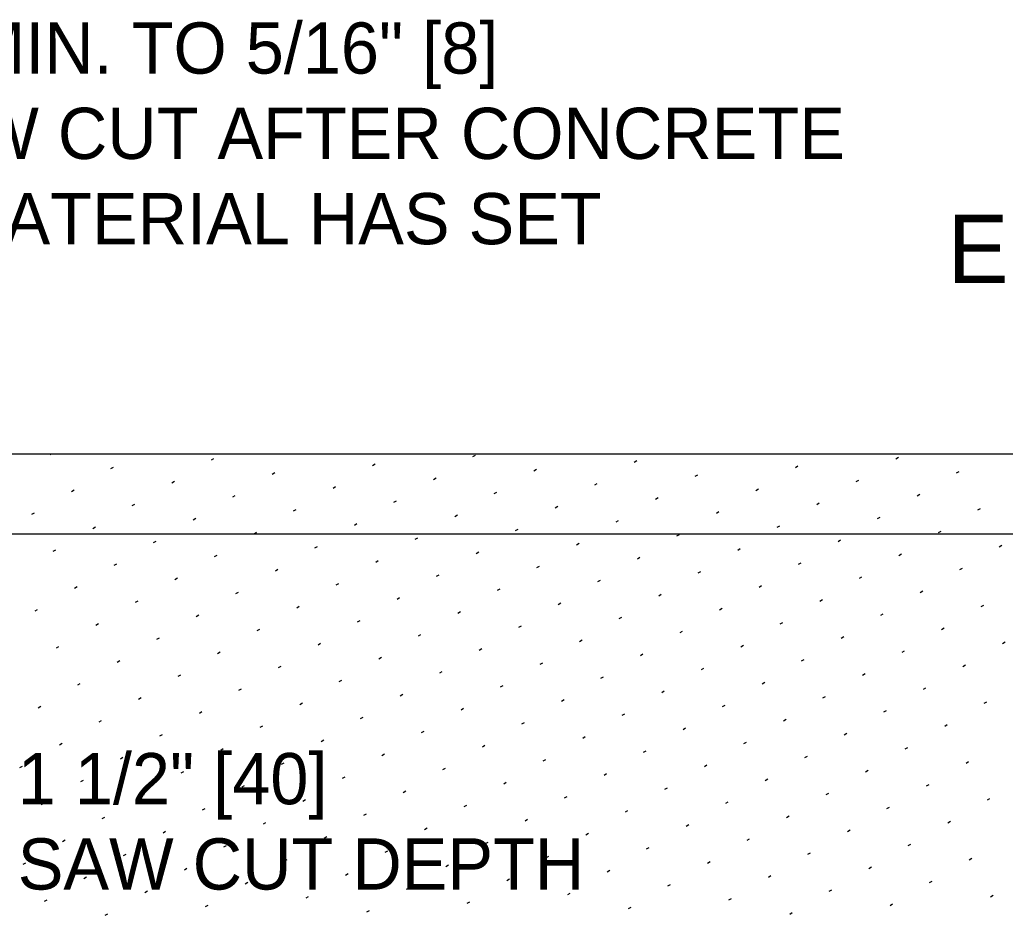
# Model space of a CAD drawing. Extents: x 49991.4 to 50021, y 49987.6 to 50011.4.
# Drawn here: x 50008.715 to 50009.87, y 49994.336 to 49995.386 of the extents above; entities that cross this region are included whole.
import ezdxf

# ---------------------------------------------------------------- set-up
doc = ezdxf.new("R2010")
doc.units = 0
for name, color, linetype in [('Level 1', 7, 'Continuous'), ('Level 2', 7, 'Continuous'), ('Level 3', 7, 'Continuous'), ('Level 6', 7, 'Continuous')]:
    doc.layers.add(name, color=color, linetype=linetype)

msp = doc.modelspace()

# ---------------------------------------------------------------- linework, layer by layer
at = {"layer": 'Level 1'}
msp.add_line((50008.1053, 49994.8772), (50011.6646, 49994.8772), dxfattribs=at)
at = {"layer": 'Level 3'}
for p, q in [((50008.7505, 49994.8763), (50008.7521, 49994.8772)), ((50008.9395, 49994.8699), (50008.9425, 49994.8717)), ((50009.2462, 49994.8738), (50009.2492, 49994.8755)), ((50009.4352, 49994.8674), (50009.4382, 49994.8692)), ((50009.7419, 49994.8713), (50009.7449, 49994.8731)), ((50008.8218, 49994.8597), (50008.8248, 49994.8615)), ((50009.1285, 49994.8636), (50009.1315, 49994.8653)), ((50009.3175, 49994.8572), (50009.3205, 49994.859)), ((50009.6242, 49994.8611), (50009.6272, 49994.8629)), ((50009.8132, 49994.8548), (50009.8163, 49994.8565)), ((50008.8931, 49994.8432), (50008.8962, 49994.8449)), ((50009.0108, 49994.8534), (50009.0139, 49994.8551)), ((50009.1998, 49994.847), (50009.2029, 49994.8488)), ((50009.5065, 49994.8509), (50009.5096, 49994.8526)), ((50009.6955, 49994.8446), (50009.6986, 49994.8463)), ((50008.7755, 49994.833), (50008.7785, 49994.8347)), ((50009.0822, 49994.8368), (50009.0852, 49994.8386)), ((50009.3889, 49994.8407), (50009.3919, 49994.8424)), ((50009.5779, 49994.8343), (50009.5809, 49994.8361)), ((50008.9645, 49994.8266), (50008.9675, 49994.8284)), ((50009.1535, 49994.8203), (50009.1565, 49994.822)), ((50009.2712, 49994.8305), (50009.2742, 49994.8322)), ((50009.4602, 49994.8241), (50009.4632, 49994.8259)), ((50009.7669, 49994.828), (50009.7699, 49994.8298)), ((50008.8468, 49994.8164), (50008.8498, 49994.8182)), ((50009.0358, 49994.8101), (50009.0389, 49994.8118)), ((50009.3425, 49994.8139), (50009.3455, 49994.8157)), ((50009.5315, 49994.8076), (50009.5346, 49994.8093)), ((50009.6492, 49994.8178), (50009.6522, 49994.8196)), ((50009.8382, 49994.8115), (50009.8413, 49994.8132)), ((50008.7291, 49994.8062), (50008.7322, 49994.808)), ((50008.9181, 49994.7999), (50008.9212, 49994.8016)), ((50009.2248, 49994.8037), (50009.2279, 49994.8055)), ((50009.4139, 49994.7974), (50009.4169, 49994.7991)), ((50009.7205, 49994.8013), (50009.7236, 49994.803)), ((50008.8005, 49994.7897), (50008.8035, 49994.7914)), ((50009.1072, 49994.7935), (50009.1102, 49994.7953)), ((50009.2962, 49994.7872), (50009.2992, 49994.7889)), ((50009.6029, 49994.791), (50009.6059, 49994.7928)), ((50009.7919, 49994.7847), (50009.7949, 49994.7865)), ((50008.8718, 49994.7731), (50008.8748, 49994.7749)), ((50008.9895, 49994.7833), (50008.9925, 49994.7851)), ((50009.1785, 49994.777), (50009.1815, 49994.7787)), ((50009.4852, 49994.7808), (50009.4882, 49994.7826)), ((50009.6742, 49994.7745), (50009.6772, 49994.7762)), ((50008.7541, 49994.7629), (50008.7572, 49994.7647)), ((50009.0608, 49994.7668), (50009.0639, 49994.7685)), ((50009.3675, 49994.7706), (50009.3705, 49994.7724)), ((50009.5565, 49994.7643), (50009.5596, 49994.766)), ((50009.8632, 49994.7682), (50009.8663, 49994.7699)), ((50008.9431, 49994.7566), (50008.9462, 49994.7583)), ((50009.1322, 49994.7502), (50009.1352, 49994.752)), ((50009.2498, 49994.7604), (50009.2529, 49994.7622)), ((50009.4389, 49994.7541), (50009.4419, 49994.7558)), ((50009.7455, 49994.758), (50009.7486, 49994.7597)), ((50008.8255, 49994.7464), (50008.8285, 49994.7481)), ((50009.0145, 49994.74), (50009.0175, 49994.7418)), ((50009.3212, 49994.7439), (50009.3242, 49994.7456)), ((50009.6279, 49994.7477), (50009.6309, 49994.7495)), ((50009.8169, 49994.7414), (50009.8199, 49994.7432)), ((50008.8968, 49994.7298), (50008.8998, 49994.7316)), ((50009.2035, 49994.7337), (50009.2065, 49994.7354)), ((50009.3925, 49994.7273), (50009.3955, 49994.7291)), ((50009.5102, 49994.7375), (50009.5132, 49994.7393)), ((50009.6992, 49994.7312), (50009.7022, 49994.7329)), ((50008.7791, 49994.7196), (50008.7822, 49994.7214)), ((50009.0858, 49994.7235), (50009.0889, 49994.7252)), ((50009.2748, 49994.7171), (50009.2779, 49994.7189)), ((50009.5815, 49994.721), (50009.5846, 49994.7227)), ((50008.9681, 49994.7133), (50008.9712, 49994.715)), ((50009.1572, 49994.7069), (50009.1602, 49994.7087)), ((50009.4639, 49994.7108), (50009.4669, 49994.7125)), ((50009.6529, 49994.7044), (50009.6559, 49994.7062)), ((50009.7705, 49994.7147), (50009.7736, 49994.7164)), ((50008.7328, 49994.6929), (50008.7358, 49994.6946)), ((50008.8505, 49994.7031), (50008.8535, 49994.7048)), ((50009.0395, 49994.6967), (50009.0425, 49994.6985)), ((50009.3462, 49994.7006), (50009.3492, 49994.7023)), ((50009.5352, 49994.6942), (50009.5382, 49994.696)), ((50009.8419, 49994.6981), (50009.8449, 49994.6999)), ((50008.9218, 49994.6865), (50008.9248, 49994.6883)), ((50009.2285, 49994.6904), (50009.2315, 49994.6921)), ((50009.4175, 49994.684), (50009.4205, 49994.6858)), ((50009.7242, 49994.6879), (50009.7272, 49994.6896)), ((50008.8041, 49994.6763), (50008.8072, 49994.6781)), ((50008.9931, 49994.67), (50008.9962, 49994.6717)), ((50009.1108, 49994.6802), (50009.1139, 49994.6819)), ((50009.2998, 49994.6738), (50009.3029, 49994.6756)), ((50009.6065, 49994.6777), (50009.6096, 49994.6794)), ((50009.7955, 49994.6713), (50009.7986, 49994.6731)), ((50008.8755, 49994.6598), (50008.8785, 49994.6615)), ((50009.1822, 49994.6636), (50009.1852, 49994.6654)), ((50009.4889, 49994.6675), (50009.4919, 49994.6692)), ((50009.6779, 49994.6611), (50009.6809, 49994.6629)), ((50008.7578, 49994.6496), (50008.7608, 49994.6513)), ((50009.0645, 49994.6534), (50009.0675, 49994.6552)), ((50009.2535, 49994.6471), (50009.2565, 49994.6488)), ((50009.3712, 49994.6573), (50009.3742, 49994.659)), ((50009.5602, 49994.6509), (50009.5632, 49994.6527)), ((50009.8669, 49994.6548), (50009.8699, 49994.6566)), ((50008.9468, 49994.6432), (50008.9498, 49994.645)), ((50009.1358, 49994.6369), (50009.1389, 49994.6386)), ((50009.4425, 49994.6407), (50009.4455, 49994.6425)), ((50009.6315, 49994.6344), (50009.6346, 49994.6361)), ((50009.7492, 49994.6446), (50009.7522, 49994.6463)), ((50008.8291, 49994.633), (50008.8322, 49994.6348)), ((50009.0181, 49994.6267), (50009.0212, 49994.6284)), ((50009.3248, 49994.6305), (50009.3279, 49994.6323)), ((50009.5139, 49994.6242), (50009.5169, 49994.6259)), ((50009.8205, 49994.628), (50009.8236, 49994.6298)), ((50008.9005, 49994.6165), (50008.9035, 49994.6182)), ((50009.2072, 49994.6203), (50009.2102, 49994.6221)), ((50009.3962, 49994.614), (50009.3992, 49994.6157)), ((50009.7029, 49994.6178), (50009.7059, 49994.6196)), ((50008.7828, 49994.6063), (50008.7858, 49994.608)), ((50008.9718, 49994.5999), (50008.9748, 49994.6017)), ((50009.0895, 49994.6101), (50009.0925, 49994.6119)), ((50009.2785, 49994.6038), (50009.2815, 49994.6055)), ((50009.5852, 49994.6076), (50009.5882, 49994.6094)), ((50009.7742, 49994.6013), (50009.7772, 49994.603)), ((50008.8541, 49994.5897), (50008.8572, 49994.5915)), ((50009.1608, 49994.5936), (50009.1639, 49994.5953)), ((50009.4675, 49994.5974), (50009.4705, 49994.5992)), ((50009.6565, 49994.5911), (50009.6596, 49994.5928)), ((50008.7365, 49994.5795), (50008.7395, 49994.5812)), ((50009.0431, 49994.5834), (50009.0462, 49994.5851)), ((50009.2322, 49994.577), (50009.2352, 49994.5788)), ((50009.3498, 49994.5872), (50009.3529, 49994.589)), ((50009.5389, 49994.5809), (50009.5419, 49994.5826)), ((50009.8455, 49994.5847), (50009.8486, 49994.5865)), ((50008.9255, 49994.5732), (50008.9285, 49994.5749)), ((50009.1145, 49994.5668), (50009.1175, 49994.5686)), ((50009.4212, 49994.5707), (50009.4242, 49994.5724)), ((50009.7279, 49994.5745), (50009.7309, 49994.5763)), ((50008.8078, 49994.563), (50008.8108, 49994.5647)), ((50008.9968, 49994.5566), (50008.9998, 49994.5584)), ((50009.3035, 49994.5605), (50009.3065, 49994.5622)), ((50009.4925, 49994.5541), (50009.4955, 49994.5559)), ((50009.6102, 49994.5643), (50009.6132, 49994.5661)), ((50009.7992, 49994.558), (50009.8022, 49994.5597)), ((50008.8791, 49994.5464), (50008.8822, 49994.5482)), ((50009.1858, 49994.5503), (50009.1889, 49994.552)), ((50009.3748, 49994.5439), (50009.3779, 49994.5457)), ((50009.6815, 49994.5478), (50009.6846, 49994.5495)), ((50008.7615, 49994.5362), (50008.7645, 49994.5379)), ((50009.0681, 49994.5401), (50009.0712, 49994.5418)), ((50009.2572, 49994.5337), (50009.2602, 49994.5355)), ((50009.5639, 49994.5376), (50009.5669, 49994.5393)), ((50009.7529, 49994.5312), (50009.7559, 49994.533)), ((50008.8328, 49994.5196), (50008.8358, 49994.5214)), ((50008.9505, 49994.5299), (50008.9535, 49994.5316)), ((50009.1395, 49994.5235), (50009.1425, 49994.5253)), ((50009.4462, 49994.5274), (50009.4492, 49994.5291)), ((50009.6352, 49994.521), (50009.6382, 49994.5228)), ((50008.7151, 49994.5094), (50008.7181, 49994.5112)), ((50009.0218, 49994.5133), (50009.0248, 49994.5151)), ((50009.3285, 49994.5172), (50009.3315, 49994.5189)), ((50009.5175, 49994.5108), (50009.5205, 49994.5126)), ((50009.8242, 49994.5147), (50009.8272, 49994.5164)), ((50008.9041, 49994.5031), (50008.9072, 49994.5049)), ((50009.0931, 49994.4968), (50009.0962, 49994.4985)), ((50009.2108, 49994.507), (50009.2139, 49994.5087)), ((50009.3998, 49994.5006), (50009.4029, 49994.5024)), ((50009.7065, 49994.5045), (50009.7096, 49994.5062)), ((50008.7865, 49994.4929), (50008.7895, 49994.4946)), ((50008.9755, 49994.4866), (50008.9785, 49994.4883)), ((50009.2822, 49994.4904), (50009.2852, 49994.4922)), ((50009.4712, 49994.4841), (50009.4742, 49994.4858)), ((50009.5889, 49994.4943), (50009.5919, 49994.496)), ((50009.7779, 49994.4879), (50009.7809, 49994.4897)), ((50008.8578, 49994.4763), (50008.8608, 49994.4781)), ((50009.1645, 49994.4802), (50009.1675, 49994.482)), ((50009.3535, 49994.4739), (50009.3565, 49994.4756)), ((50009.6602, 49994.4777), (50009.6632, 49994.4795)), ((50008.7401, 49994.4661), (50008.7431, 49994.4679)), ((50009.0468, 49994.47), (50009.0498, 49994.4718)), ((50009.2358, 49994.4637), (50009.2389, 49994.4654)), ((50009.5425, 49994.4675), (50009.5455, 49994.4693)), ((50009.7315, 49994.4612), (50009.7346, 49994.4629)), ((50009.8492, 49994.4714), (50009.8522, 49994.4731)), ((50008.8115, 49994.4496), (50008.8145, 49994.4513)), ((50008.9291, 49994.4598), (50008.9322, 49994.4615)), ((50009.1181, 49994.4535), (50009.1212, 49994.4552)), ((50009.4248, 49994.4573), (50009.4279, 49994.4591)), ((50009.6139, 49994.451), (50009.6169, 49994.4527)), ((50009.0005, 49994.4433), (50009.0035, 49994.445)), ((50009.3072, 49994.4471), (50009.3102, 49994.4489)), ((50009.4962, 49994.4408), (50009.4992, 49994.4425)), ((50009.8029, 49994.4446), (50009.8059, 49994.4464)), ((50008.8828, 49994.433), (50008.8858, 49994.4348)), ((50009.0718, 49994.4267), (50009.0748, 49994.4285)), ((50009.1895, 49994.4369), (50009.1925, 49994.4387)), ((50009.3785, 49994.4306), (50009.3815, 49994.4323)), ((50009.6852, 49994.4344), (50009.6882, 49994.4362)), ((50008.7651, 49994.4228), (50008.7681, 49994.4246)), ((50008.9541, 49994.4165), (50008.9572, 49994.4182)), ((50009.2608, 49994.4204), (50009.2639, 49994.4221)), ((50009.5675, 49994.4242), (50009.5705, 49994.426)), ((50009.7565, 49994.4179), (50009.7596, 49994.4196)), ((50008.8365, 49994.4063), (50008.8395, 49994.408)), ((50009.1431, 49994.4102), (50009.1462, 49994.4119)), ((50009.3322, 49994.4038), (50009.3352, 49994.4056)), ((50009.4498, 49994.414), (50009.4529, 49994.4158)), ((50009.6389, 49994.4077), (50009.6419, 49994.4094)), ((50008.7188, 49994.3961), (50008.7218, 49994.3978)), ((50009.0255, 49994.4), (50009.0285, 49994.4017)), ((50009.2145, 49994.3936), (50009.2175, 49994.3954)), ((50009.5212, 49994.3975), (50009.5242, 49994.3992)), ((50009.8279, 49994.4013), (50009.8309, 49994.4031)), ((50008.9078, 49994.3897), (50008.9108, 49994.3915)), ((50009.0968, 49994.3834), (50009.0998, 49994.3852)), ((50009.4035, 49994.3873), (50009.4065, 49994.389)), ((50009.5925, 49994.3809), (50009.5955, 49994.3827)), ((50009.7102, 49994.3911), (50009.7132, 49994.3929)), ((50008.7901, 49994.3795), (50008.7931, 49994.3813)), ((50008.9791, 49994.3732), (50008.9822, 49994.3749)), ((50009.2858, 49994.3771), (50009.2889, 49994.3788)), ((50009.4748, 49994.3707), (50009.4779, 49994.3725)), ((50009.7815, 49994.3746), (50009.7846, 49994.3763)), ((50008.8615, 49994.363), (50008.8645, 49994.3647)), ((50009.1681, 49994.3669), (50009.1712, 49994.3686)), ((50009.3572, 49994.3605), (50009.3602, 49994.3623)), ((50009.6639, 49994.3644), (50009.6669, 49994.3661)), ((50009.8529, 49994.358), (50009.8559, 49994.3598)), ((50008.7438, 49994.3528), (50008.7468, 49994.3545)), ((50008.9328, 49994.3464), (50008.9358, 49994.3482)), ((50009.0505, 49994.3566), (50009.0535, 49994.3584)), ((50009.2395, 49994.3503), (50009.2425, 49994.3521)), ((50009.5462, 49994.3542), (50009.5492, 49994.3559)), ((50009.7352, 49994.3478), (50009.7382, 49994.3496)), ((50008.8151, 49994.3362), (50008.8181, 49994.338)), ((50009.1218, 49994.3401), (50009.1248, 49994.3419)), ((50009.4285, 49994.344), (50009.4315, 49994.3457)), ((50009.6175, 49994.3376), (50009.6205, 49994.3394))]:
    msp.add_line(p, q, dxfattribs=at)
at = {"layer": 'Level 6'}
msp.add_line((50014.3722, 49994.7828), (50008.1053, 49994.7828), dxfattribs=at)

# ---------------------------------------------------------------- texts
at = {"layer": 'Level 2'}
for s, height, p in [('3/16" [5] MIN. TO 5/16" [8]', 0.06, (50008.336, 49995.3227)), ('MAX. SAW CUT AFTER CONCRETE ', 0.06, (50008.336, 49995.2227)), ('PATCH MATERIAL HAS SET', 0.06, (50008.336, 49995.1227)), ('E', 0.08, (50009.8026, 49995.0772)), ('1 1/2" [40]', 0.06, (50008.7125, 49994.4664)), ('SAW CUT DEPTH', 0.06, (50008.7125, 49994.3664))]:
    msp.add_text(s, height=height, dxfattribs=at).set_placement(p)

doc.saveas('drawing.dxf')
